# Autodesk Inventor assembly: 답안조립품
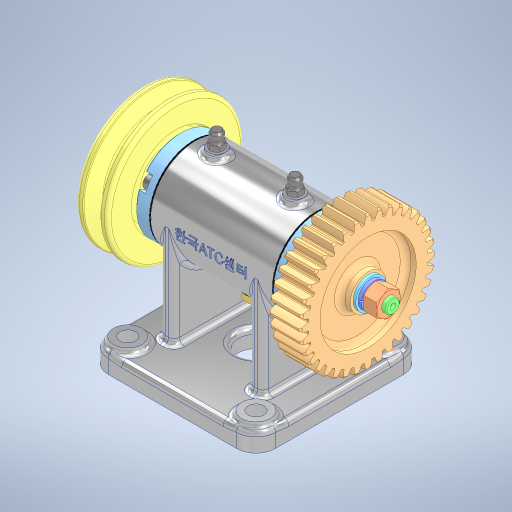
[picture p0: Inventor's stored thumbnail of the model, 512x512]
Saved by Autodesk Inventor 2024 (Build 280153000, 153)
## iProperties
Created: 2025-10
Part Number: 답안조립품
Document SubType Name: Assembly
Designer: EDU03
Author: EDU03
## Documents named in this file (17)
- C:\Users\EDU03\Desktop\751003V1002\답안조립품.iam
- C:\Users\EDU03\Desktop\751003V1002\본체.ipt
- C:\Users\EDU03\Desktop\751003V1002\축\축.ipt
- C:\Users\EDU03\Desktop\751003V1002\평행 키 3x3x12\평행 키 3x3x12.ipt
- C:\Users\EDU03\Desktop\751003V1002\깊은 홈 볼 베어링 6002\깊은 홈 볼 베어링 6002.ipt
- C:\Users\EDU03\Desktop\751003V1002\커버\커버.ipt
- C:\Users\EDU03\Desktop\751003V1002\오일 실 15 25 4\오일 실 15 25 4.ipt
- C:\Users\EDU03\Desktop\751003V1002\가스켓\가스켓.ipt
- C:\Users\EDU03\Desktop\751003V1002\스퍼 기어\스퍼 기어.ipt
- C:\Users\EDU03\Desktop\751003V1002\V 벨트 풀리\V 벨트 풀리.ipt
- C:\Users\EDU03\Desktop\751003V1002\평 와셔 M8\평 와셔 M8.ipt
- C:\Users\EDU03\Desktop\751003V1002\스프링 와셔 M8\스프링 와셔 M8.ipt
- C:\Users\EDU03\Desktop\751003V1002\6각 너트 M8x1\6각 너트 M8x1.ipt
- C:\Users\EDU03\Desktop\751003V1002\실링\실링.ipt
- C:\Users\EDU03\Desktop\751003V1002\6각 머리 볼트 M6x0.75x8\6각 머리 볼트 M6x0.75x8.ipt
- C:\Users\EDU03\Desktop\751003V1002\6각 구멍붙이 볼트 M4x10\6각 구멍붙이 볼트 M4x10.ipt
- C:\Users\EDU03\Desktop\751003V1002\그리스 니플 M6x0.75\그리스 니플 M6x0.75.ipt
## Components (14 placed, 6 different names)
1. 가스켓:1
2. 가스켓:2
3. V 벨트 풀리:1
4. 6각 너트 M8x1:1
5. 6각 너트 M8x1:2
6. 6각 머리 볼트 M6x0.75x8:1
7. 6각 구멍붙이 볼트 M4x10:1
8. 6각 구멍붙이 볼트 M4x10:2
9. 6각 구멍붙이 볼트 M4x10:3
10. 6각 구멍붙이 볼트 M4x10:4
11. 6각 구멍붙이 볼트 M4x10:5
12. 6각 구멍붙이 볼트 M4x10:6
13. 그리스 니플 M6x0.75:1
14. 그리스 니플 M6x0.75:2
